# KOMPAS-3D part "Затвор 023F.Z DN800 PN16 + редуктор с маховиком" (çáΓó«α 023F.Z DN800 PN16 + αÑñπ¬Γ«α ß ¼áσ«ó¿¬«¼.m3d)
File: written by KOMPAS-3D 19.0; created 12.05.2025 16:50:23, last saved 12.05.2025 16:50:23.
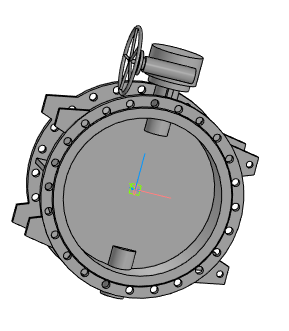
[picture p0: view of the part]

Document properties: Полное имя файла: Затвор 023F.Z DN800 PN16 + редуктор с маховиком.a3d

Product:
- Part/product: Затвор 023F.Z DN800 PN16 + редуктор с маховиком
    Масса: 787.281

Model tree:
1. Операция без истории:1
